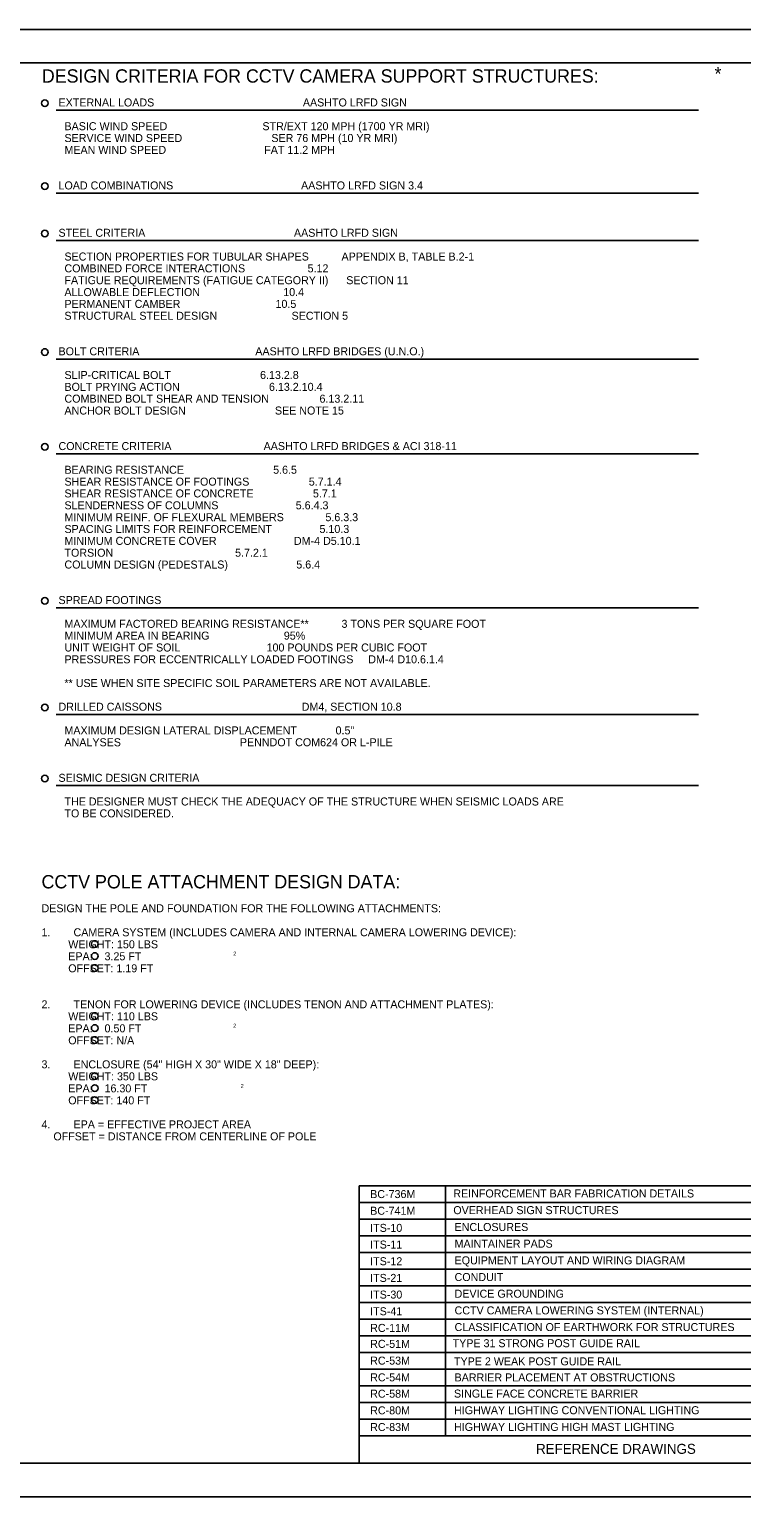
# Model space of a CAD drawing. Extents: x 1299105.1 to 1299141.9, y 239690 to 239712.
# Drawn here: x 1299117.55 to 1299128.23, y 239689.98 to 239711.98 of the extents above; entities that cross this region are included whole.
import ezdxf

# ---------------------------------------------------------------- set-up
doc = ezdxf.new("R2010")
doc.units = 0
for name, color, linetype in [('DIM TXT', 7, 'Continuous'), ('GS_plotshape_p', 7, 'Continuous'), ('Level 1', 7, 'Continuous')]:
    doc.layers.add(name, color=color, linetype=linetype)

msp = doc.modelspace()

# ---------------------------------------------------------------- linework, layer by layer
at = {"layer": 'DIM TXT'}
for p, q in [((1299117.952, 239710.771), (1299127.583, 239710.771)), ((1299117.952, 239709.527), (1299127.583, 239709.527)), ((1299117.952, 239708.817), (1299127.583, 239708.817)), ((1299117.952, 239707.04), (1299127.583, 239707.04)), ((1299117.952, 239705.619), (1299127.583, 239705.619)), ((1299117.952, 239703.31), (1299127.583, 239703.31)), ((1299117.952, 239701.711), (1299127.583, 239701.711)), ((1299117.952, 239700.645), (1299127.583, 239700.645)), ((1299122.492, 239690.484), (1299122.492, 239694.646)), ((1299122.492, 239694.646), (1299130.59, 239694.646)), ((1299123.791, 239690.896), (1299123.791, 239694.646)), ((1299122.492, 239694.396), (1299130.59, 239694.396)), ((1299122.492, 239694.146), (1299130.59, 239694.146)), ((1299122.492, 239693.896), (1299130.59, 239693.896)), ((1299122.492, 239693.646), (1299130.59, 239693.646)), ((1299122.492, 239693.396), (1299130.59, 239693.396)), ((1299122.492, 239693.146), (1299130.59, 239693.146)), ((1299122.492, 239692.896), (1299130.59, 239692.896)), ((1299122.492, 239692.646), (1299130.59, 239692.646)), ((1299122.492, 239692.396), (1299130.59, 239692.396)), ((1299122.492, 239692.146), (1299130.59, 239692.146)), ((1299122.492, 239691.896), (1299130.59, 239691.896)), ((1299122.492, 239691.646), (1299130.59, 239691.646)), ((1299122.492, 239691.396), (1299130.59, 239691.396)), ((1299122.492, 239691.146), (1299130.59, 239691.146)), ((1299122.492, 239690.896), (1299130.59, 239690.896))]:
    msp.add_line(p, q, dxfattribs=at)
for centre in [(1299117.78, 239710.877), (1299117.78, 239709.633), (1299117.78, 239708.923), (1299117.78, 239707.146), (1299117.78, 239705.725), (1299117.78, 239703.416), (1299117.78, 239701.817), (1299117.78, 239700.751), (1299118.528, 239698.27), (1299118.528, 239698.09), (1299118.528, 239697.91), (1299118.528, 239697.91), (1299118.528, 239697.19), (1299118.528, 239697.01), (1299118.528, 239696.83), (1299118.528, 239696.83), (1299118.528, 239696.29), (1299118.528, 239696.11), (1299118.528, 239695.93), (1299118.528, 239695.93)]:
    msp.add_circle(centre, 0.05, dxfattribs=at)
at = {"layer": 'GS_plotshape_p'}
msp.add_lwpolyline([(1299105.09, 239711.984), (1299139.09, 239711.984), (1299139.09, 239689.984), (1299105.09, 239689.984)], close=True, dxfattribs=at)
at = {"layer": 'Level 1'}
msp.add_lwpolyline([(1299138.59, 239690.484), (1299106.59, 239690.484), (1299106.59, 239711.484), (1299138.59, 239711.484)], close=True, dxfattribs=at)

# ---------------------------------------------------------------- texts
at = {"layer": 'DIM TXT'}
for s, height, p in [('DESIGN CRITERIA FOR CCTV CAMERA SUPPORT STRUCTURES:', 0.2, (1299117.735, 239711.185)), ('*', 0.2, (1299127.824, 239711.219)), ('EXTERNAL LOADS                                                  AASHTO LRFD SIGN', 0.12, (1299117.985, 239710.828)), ('  BASIC WIND SPEED                                STR/EXT 120 MPH (1700 YR MRI)', 0.12, (1299117.985, 239710.472)), ('  SERVICE WIND SPEED                              SER 76 MPH (10 YR MRI)', 0.12, (1299117.985, 239710.295)), ('  MEAN WIND SPEED                                 FAT 11.2 MPH', 0.12, (1299117.985, 239710.117)), ('LOAD COMBINATIONS                                           AASHTO LRFD SIGN 3.4', 0.12, (1299117.985, 239709.584)), ('STEEL CRITERIA                                                  AASHTO LRFD SIGN', 0.12, (1299117.985, 239708.874)), ('  SECTION PROPERTIES FOR TUBULAR SHAPES           APPENDIX B, TABLE B.2-1', 0.12, (1299117.985, 239708.518)), ('  COMBINED FORCE INTERACTIONS                     5.12', 0.12, (1299117.985, 239708.341)), ('  FATIGUE REQUIREMENTS (FATIGUE CATEGORY II)      SECTION 11', 0.12, (1299117.985, 239708.163)), ('  ALLOWABLE DEFLECTION                            10.4', 0.12, (1299117.985, 239707.985)), ('  PERMANENT CAMBER                                10.5', 0.12, (1299117.985, 239707.808)), ('  STRUCTURAL STEEL DESIGN                         SECTION 5', 0.12, (1299117.985, 239707.63)), ('BOLT CRITERIA                                       AASHTO LRFD BRIDGES (U.N.O.)', 0.12, (1299117.985, 239707.097)), ('  SLIP-CRITICAL BOLT                              6.13.2.8', 0.12, (1299117.985, 239706.742)), ('  COMBINED BOLT SHEAR AND TENSION                 6.13.2.11', 0.12, (1299117.985, 239706.387)), ('  BOLT PRYING ACTION                              6.13.2.10.4', 0.12, (1299117.985, 239706.564)), ('  ANCHOR BOLT DESIGN                              SEE NOTE 15', 0.12, (1299117.985, 239706.209)), ('CONCRETE CRITERIA                               AASHTO LRFD BRIDGES & ACI 318-11', 0.12, (1299117.985, 239705.676)), ('  BEARING RESISTANCE                              5.6.5', 0.12, (1299117.985, 239705.321)), ('  SHEAR RESISTANCE OF FOOTINGS                    5.7.1.4', 0.12, (1299117.985, 239705.143)), ('  SHEAR RESISTANCE OF CONCRETE                    5.7.1', 0.12, (1299117.985, 239704.966)), ('  SLENDERNESS OF COLUMNS                          5.6.4.3', 0.12, (1299117.985, 239704.788)), ('  SPACING LIMITS FOR REINFORCEMENT                5.10.3', 0.12, (1299117.985, 239704.433)), ('  MINIMUM REINF. OF FLEXURAL MEMBERS              5.6.3.3', 0.12, (1299117.985, 239704.61)), ('  MINIMUM CONCRETE COVER                          DM-4 D5.10.1', 0.12, (1299117.985, 239704.255)), ('  TORSION                                         5.7.2.1', 0.12, (1299117.985, 239704.077)), ('  COLUMN DESIGN (PEDESTALS)                       5.6.4', 0.12, (1299117.985, 239703.9)), ('SPREAD FOOTINGS', 0.12, (1299117.985, 239703.367)), ('  MAXIMUM FACTORED BEARING RESISTANCE**           3 TONS PER SQUARE FOOT', 0.12, (1299117.985, 239703.011)), ('  UNIT WEIGHT OF SOIL                             100 POUNDS PER CUBIC FOOT', 0.12, (1299117.985, 239702.656)), ('  MINIMUM AREA IN BEARING                         95%', 0.12, (1299117.985, 239702.834)), ('  PRESSURES FOR ECCENTRICALLY LOADED FOOTINGS     DM-4 D10.6.1.4', 0.12, (1299117.985, 239702.479)), ('  ** USE WHEN SITE SPECIFIC SOIL PARAMETERS ARE NOT AVAILABLE.', 0.12, (1299117.985, 239702.123)), ('DRILLED CAISSONS                                               DM4, SECTION 10.8', 0.12, (1299117.985, 239701.768)), ('  MAXIMUM DESIGN LATERAL DISPLACEMENT             0.5"', 0.12, (1299117.985, 239701.413)), ('  ANALYSES                                        PENNDOT COM624 OR L-PILE', 0.12, (1299117.985, 239701.235)), ('SEISMIC DESIGN CRITERIA', 0.12, (1299117.985, 239700.702)), ('  THE DESIGNER MUST CHECK THE ADEQUACY OF THE STRUCTURE WHEN SEISMIC LOADS ARE', 0.12, (1299117.985, 239700.347)), ('  TO BE CONSIDERED.', 0.12, (1299117.985, 239700.169)), ('CCTV POLE ATTACHMENT DESIGN DATA:', 0.2, (1299117.73, 239699.104)), ('DESIGN THE POLE AND FOUNDATION FOR THE FOLLOWING ATTACHMENTS:', 0.12, (1299117.73, 239698.746)), ('1.', 0.12, (1299117.73, 239698.386)), ('CAMERA SYSTEM (INCLUDES CAMERA AND INTERNAL CAMERA LOWERING DEVICE):', 0.12, (1299118.21, 239698.386)), ('         WEIGHT: 150 LBS', 0.12, (1299117.73, 239698.206)), ('         EPA:    3.25 FT', 0.12, (1299117.73, 239698.026)), ('2', 0.06, (1299120.606, 239698.095)), ('         OFFSET: 1.19 FT', 0.12, (1299117.73, 239697.846)), ('2.', 0.12, (1299117.73, 239697.306)), ('TENON FOR LOWERING DEVICE (INCLUDES TENON AND ATTACHMENT PLATES):', 0.12, (1299118.21, 239697.306)), ('         WEIGHT: 110 LBS', 0.12, (1299117.73, 239697.126)), ('         EPA:    0.50 FT', 0.12, (1299117.73, 239696.946)), ('2', 0.06, (1299120.604, 239697.015)), ('         OFFSET: N/A', 0.12, (1299117.73, 239696.766)), ('3.', 0.12, (1299117.73, 239696.406)), ('ENCLOSURE (54" HIGH X 30" WIDE X 18" DEEP):', 0.12, (1299118.21, 239696.406)), ('         WEIGHT: 350 LBS', 0.12, (1299117.73, 239696.226)), ('         EPA:    16.30 FT', 0.12, (1299117.73, 239696.046)), ('2', 0.06, (1299120.716, 239696.111)), ('         OFFSET: 140 FT', 0.12, (1299117.73, 239695.866)), ('4.', 0.12, (1299117.73, 239695.506)), ('EPA = EFFECTIVE PROJECT AREA', 0.12, (1299118.21, 239695.506)), ('    OFFSET = DISTANCE FROM CENTERLINE OF POLE', 0.12, (1299117.73, 239695.326)), ('BC-736M', 0.12, (1299122.659, 239694.461)), ('REINFORCEMENT BAR FABRICATION DETAILS', 0.12, (1299123.906, 239694.47)), ('BC-741M', 0.12, (1299122.659, 239694.211)), ('OVERHEAD SIGN STRUCTURES', 0.12, (1299123.906, 239694.22)), ('ITS-10', 0.12, (1299122.659, 239693.954)), ('ENCLOSURES', 0.12, (1299123.925, 239693.967)), ('ITS-11', 0.12, (1299122.659, 239693.704)), ('MAINTAINER PADS', 0.12, (1299123.925, 239693.717)), ('ITS-12', 0.12, (1299122.659, 239693.454)), ('EQUIPMENT LAYOUT AND WIRING DIAGRAM', 0.12, (1299123.925, 239693.467)), ('ITS-21', 0.12, (1299122.659, 239693.204)), ('CONDUIT', 0.12, (1299123.925, 239693.217)), ('DEVICE GROUNDING', 0.12, (1299123.925, 239692.967)), ('ITS-30', 0.12, (1299122.659, 239692.954)), ('ITS-41', 0.12, (1299122.659, 239692.704)), ('CCTV CAMERA LOWERING SYSTEM (INTERNAL)', 0.12, (1299123.925, 239692.717)), ('RC-11M', 0.12, (1299122.659, 239692.454)), ('CLASSIFICATION OF EARTHWORK FOR STRUCTURES', 0.12, (1299123.925, 239692.467)), ('RC-51M', 0.12, (1299122.659, 239692.215)), ('TYPE 31 STRONG POST GUIDE RAIL', 0.12, (1299123.896, 239692.225)), ('RC-53M', 0.12, (1299122.659, 239691.964)), ('TYPE 2 WEAK POST GUIDE RAIL', 0.12, (1299123.916, 239691.953)), ('RC-54M', 0.12, (1299122.659, 239691.713)), ('BARRIER PLACEMENT AT OBSTRUCTIONS', 0.12, (1299123.925, 239691.712)), ('RC-58M', 0.12, (1299122.659, 239691.468)), ('SINGLE FACE CONCRETE BARRIER', 0.12, (1299123.916, 239691.47)), ('RC-80M', 0.12, (1299122.659, 239691.218)), ('HIGHWAY LIGHTING CONVENTIONAL LIGHTING', 0.12, (1299123.916, 239691.22)), ('RC-83M', 0.12, (1299122.659, 239690.968)), ('HIGHWAY LIGHTING HIGH MAST LIGHTING', 0.12, (1299123.916, 239690.97)), ('REFERENCE DRAWINGS', 0.15, (1299125.147, 239690.626))]:
    msp.add_text(s, height=height, dxfattribs=at).set_placement(p)

doc.saveas('drawing.dxf')
